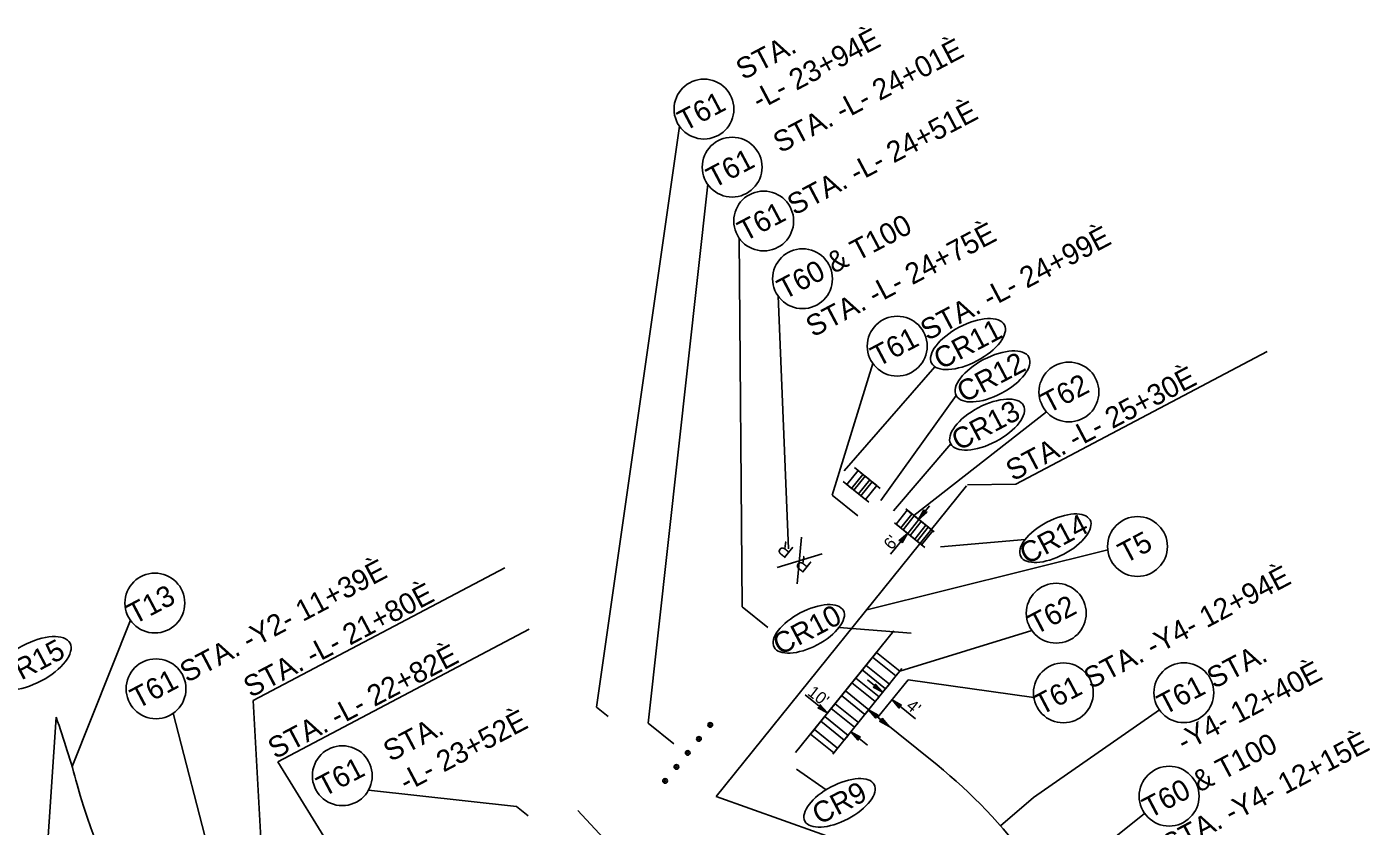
# Model space of a CAD drawing. Extents: x 1487421 to 1489048, y 497792 to 499463.
# Drawn here: x 1488599.3 to 1489047.9, y 499195.5 to 499462.7 of the extents above; entities that cross this region are included whole.
import ezdxf

# ---------------------------------------------------------------- set-up
doc = ezdxf.new("R2010")
doc.units = 0
for name, color, linetype in [('DEV TUBULAR MARKER PLAN VIEW CELL', 7, 'Continuous'), ('MARK RAILROAD SYMBOL CELL', 7, 'Continuous'), ('Prop Dimension', 7, 'Continuous'), ('Prop Mkg Min Skp 6ft White', 7, 'Continuous'), ('Prop Mkg Solid Dbl Yel Rpm 80ft', 7, 'Continuous'), ('Prop Mkg Solid White Crosswalks', 7, 'Continuous'), ('Prop Mkg Solid White Stop Bar', 7, 'Continuous'), ('Scratch_Level_3', 7, 'Continuous'), ('Scratch_Level_5', 7, 'Continuous'), ('Text', 7, 'Continuous')]:
    doc.layers.add(name, color=color, linetype=linetype)

msp = doc.modelspace()

# ---------------------------------------------------------------- linework, layer by layer
at = {"layer": 'DEV TUBULAR MARKER PLAN VIEW CELL'}
for centre, radius in [((1488827.51, 499229.29), 0.781), ((1488827.51, 499229.29), 0.332), ((1488823.74, 499224.62), 0.781), ((1488823.74, 499224.62), 0.332), ((1488819.98, 499219.95), 0.781), ((1488819.98, 499219.95), 0.332), ((1488816.21, 499215.28), 0.781), ((1488816.21, 499215.28), 0.332), ((1488812.44, 499210.61), 0.781), ((1488812.44, 499210.61), 0.332)]:
    msp.add_circle(centre, radius, dxfattribs=at)
at = {"layer": 'MARK RAILROAD SYMBOL CELL'}
for p, q in [((1488856.6, 499276.42), (1488857.96, 499292.1)), ((1488849.83, 499281.88), (1488864.87, 499286.53))]:
    msp.add_line(p, q, dxfattribs=at)
at = {"layer": 'Prop Dimension'}
for p, q in [((1488900.79, 499302.56), (1488897.12, 499298)), ((1488893.35, 499293.33), (1488887.71, 499286.34)), ((1488885.12, 499240.2), (1488879.98, 499244.35)), ((1488866.73, 499233.31), (1488859.17, 499239.4)), ((1488896.11, 499231.34), (1488888.24, 499237.69)), ((1488880.41, 499234.36), (1488887.3, 499228.8)), ((1488880.02, 499222.59), (1488874.51, 499227.04))]:
    msp.add_line(p, q, dxfattribs=at)
for points in [[(1488898.89, 499301.2), (1488897.12, 499298), (1488899.88, 499300.43), (1488899.09, 499300.47)], [(1488891.59, 499290.13), (1488893.35, 499293.33), (1488890.59, 499290.9), (1488891.38, 499290.86)], [(1488881.9, 499241.91), (1488885.12, 499240.2), (1488882.65, 499242.92), (1488882.63, 499242.13)], [(1488863.5, 499235.03), (1488866.73, 499233.31), (1488864.26, 499236.04), (1488864.23, 499235.25)], [(1488891.42, 499235.9), (1488888.24, 499237.69), (1488890.65, 499234.91), (1488890.69, 499235.7)], [(1488883.6, 499232.58), (1488880.41, 499234.36), (1488882.83, 499231.59), (1488882.87, 499232.37)], [(1488884.89, 499231.55), (1488887.3, 499228.8), (1488884.08, 499230.58), (1488884.84, 499230.79)], [(1488877.7, 499225.25), (1488874.51, 499227.04), (1488876.92, 499224.26), (1488876.96, 499225.05)]]:
    msp.add_lwpolyline(points, close=True, dxfattribs=at)
at = {"layer": 'Prop Mkg Min Skp 6ft White'}
msp.add_line((1488829.46, 499205.43), (1488913.13, 499309.18), dxfattribs=at)
at = {"layer": 'Prop Mkg Solid Dbl Yel Rpm 80ft'}
msp.add_line((1488883.53, 499231.85), (1488903.26, 499215.93), dxfattribs=at)
for centre, radius, start, end in [((1488292.94, 499121.08), 335, 15.2846, 19.3141), ((1488796.55, 499083.6), 170, 21.0099, 51.1156), ((1488809.02, 499262.12), 200, 195.2846, 229.8892)]:
    msp.add_arc(centre, radius, start, end, dxfattribs=at)
at = {"layer": 'Prop Mkg Solid White Crosswalks'}
for p, q in [((1488876.89, 499314.31), (1488873.13, 499309.64)), ((1488874.68, 499308.39), (1488878.45, 499313.06)), ((1488879.23, 499312.43), (1488875.46, 499307.76)), ((1488884.24, 499308.39), (1488875.67, 499315.3)), ((1488878.45, 499313.06), (1488876.89, 499314.31)), ((1488880.79, 499311.18), (1488879.23, 499312.43)), ((1488880.47, 499303.72), (1488871.91, 499310.63)), ((1488873.13, 499309.64), (1488874.68, 499308.39)), ((1488875.46, 499307.76), (1488877.02, 499306.51)), ((1488877.02, 499306.51), (1488880.79, 499311.18)), ((1488881.56, 499310.55), (1488877.8, 499305.88)), ((1488879.35, 499304.62), (1488883.12, 499309.29)), ((1488883.12, 499309.29), (1488881.56, 499310.55)), ((1488877.8, 499305.88), (1488879.35, 499304.62)), ((1488893.33, 499301.06), (1488889.56, 499296.39)), ((1488891.12, 499295.14), (1488894.88, 499299.81)), ((1488895.66, 499299.18), (1488891.9, 499294.51)), ((1488902.28, 499293.84), (1488892.8, 499301.49)), ((1488894.88, 499299.81), (1488893.33, 499301.06)), ((1488897.22, 499297.92), (1488895.66, 499299.18)), ((1488899.19, 499288.62), (1488889.03, 499296.82)), ((1488889.56, 499296.39), (1488891.12, 499295.14)), ((1488891.9, 499294.51), (1488893.45, 499293.25)), ((1488893.45, 499293.25), (1488897.22, 499297.92)), ((1488898, 499297.3), (1488894.23, 499292.62)), ((1488895.79, 499291.37), (1488899.55, 499296.04)), ((1488900.33, 499295.41), (1488896.57, 499290.74)), ((1488899.55, 499296.04), (1488898, 499297.3)), ((1488898.12, 499289.49), (1488901.89, 499294.16)), ((1488901.89, 499294.16), (1488900.33, 499295.41)), ((1488894.23, 499292.62), (1488895.79, 499291.37)), ((1488896.57, 499290.74), (1488898.12, 499289.49)), ((1488856.03, 499220.06), (1488888.86, 499260.76)), ((1488878.3, 499247.67), (1488879.55, 499249.22)), ((1488879.55, 499249.22), (1488878.3, 499247.67)), ((1488887.34, 499242.94), (1488879.55, 499249.22)), ((1488887.34, 499242.94), (1488879.55, 499249.22)), ((1488881.75, 499251.95), (1488883.01, 499253.5)), ((1488883.01, 499253.5), (1488881.75, 499251.95)), ((1488889.54, 499245.67), (1488881.75, 499251.95)), ((1488881.75, 499251.95), (1488889.54, 499245.67)), ((1488890.79, 499247.23), (1488883.01, 499253.5)), ((1488890.79, 499247.23), (1488883.01, 499253.5)), ((1488868.46, 499219.54), (1488891.53, 499248.14)), ((1488874.85, 499243.38), (1488876.1, 499244.94)), ((1488876.1, 499244.94), (1488874.85, 499243.38)), ((1488883.89, 499238.66), (1488876.1, 499244.94)), ((1488883.89, 499238.66), (1488876.1, 499244.94)), ((1488886.08, 499241.39), (1488878.3, 499247.67)), ((1488878.3, 499247.67), (1488886.08, 499241.39)), ((1488890.79, 499247.23), (1488889.54, 499245.67)), ((1488889.54, 499245.67), (1488890.79, 499247.23)), ((1488872.65, 499240.66), (1488871.39, 499239.1)), ((1488872.65, 499240.66), (1488871.39, 499239.1)), ((1488880.43, 499234.38), (1488872.65, 499240.66)), ((1488880.43, 499234.38), (1488872.65, 499240.66)), ((1488882.63, 499237.11), (1488874.85, 499243.38)), ((1488874.85, 499243.38), (1488882.63, 499237.11)), ((1488887.34, 499242.94), (1488886.08, 499241.39)), ((1488886.08, 499241.39), (1488887.34, 499242.94)), ((1488867.94, 499234.82), (1488869.2, 499236.38)), ((1488869.2, 499236.38), (1488867.94, 499234.82)), ((1488876.98, 499230.1), (1488869.2, 499236.38)), ((1488876.98, 499230.1), (1488869.2, 499236.38)), ((1488879.18, 499232.83), (1488871.39, 499239.1)), ((1488871.39, 499239.1), (1488879.18, 499232.83)), ((1488883.89, 499238.66), (1488882.63, 499237.11)), ((1488882.63, 499237.11), (1488883.89, 499238.66)), ((1488865.74, 499232.1), (1488864.49, 499230.54)), ((1488865.74, 499232.1), (1488864.49, 499230.54)), ((1488873.53, 499225.82), (1488865.74, 499232.1)), ((1488873.53, 499225.82), (1488865.74, 499232.1)), ((1488875.72, 499228.54), (1488867.94, 499234.82)), ((1488867.94, 499234.82), (1488875.72, 499228.54)), ((1488880.43, 499234.38), (1488879.18, 499232.83)), ((1488879.18, 499232.83), (1488880.43, 499234.38)), ((1488862.29, 499227.82), (1488861.04, 499226.26)), ((1488862.29, 499227.82), (1488861.04, 499226.26)), ((1488870.07, 499221.54), (1488862.29, 499227.82)), ((1488870.07, 499221.54), (1488862.29, 499227.82)), ((1488872.27, 499224.26), (1488864.49, 499230.54)), ((1488864.49, 499230.54), (1488872.27, 499224.26)), ((1488875.72, 499228.54), (1488876.98, 499230.1)), ((1488875.72, 499228.54), (1488876.98, 499230.1)), ((1488868.82, 499219.98), (1488861.04, 499226.26)), ((1488861.04, 499226.26), (1488868.82, 499219.98)), ((1488873.53, 499225.82), (1488872.27, 499224.26)), ((1488872.27, 499224.26), (1488873.53, 499225.82)), ((1488870.07, 499221.54), (1488868.82, 499219.98)), ((1488868.82, 499219.98), (1488870.07, 499221.54))]:
    msp.add_line(p, q, dxfattribs=at)
at = {"layer": 'Prop Mkg Solid White Stop Bar'}
for p, q in [((1488868.28, 499306.13), (1488876.84, 499299.23)), ((1488838.15, 499268.77), (1488846.72, 499261.85)), ((1488883.53, 499231.85), (1488893.6, 499244.33)), ((1488793.47, 499232.09), (1488789.58, 499235.22)), ((1488806.76, 499229.85), (1488815.34, 499222.93)), ((1488766.68, 499198.87), (1488762.79, 499202.01))]:
    msp.add_line(p, q, dxfattribs=at)
at = {"layer": 'Scratch_Level_3'}
for p, q in [((1488977.5, 499234.31), (1488935.42, 499205.07)), ((1488935.42, 499205.07), (1488924.5, 499195.52)), ((1488972.58, 499199.73), (1488950.83, 499182.38))]:
    msp.add_line(p, q, dxfattribs=at)
for centre in [(1488985.68, 499240.07), (1488980.76, 499205.49)]:
    msp.add_circle(centre, 10, dxfattribs=at)
at = {"layer": 'Scratch_Level_5'}
msp.add_line((1488883.01, 499253.5), (1488861.04, 499226.26), dxfattribs=at)
at = {"layer": 'Text'}
for p, q in [((1488817.25, 499429.4), (1488789.58, 499235.22)), ((1488826.66, 499410.01), (1488806.76, 499229.85)), ((1488837.2, 499391.99), (1488838.15, 499268.77)), ((1488850.17, 499372.69), (1488853.61, 499288.15)), ((1488929.52, 499309.82), (1489013.5, 499354.16)), ((1488881.78, 499350.17), (1488868.28, 499306.13)), ((1488872.23, 499314.22), (1488902.57, 499349.01)), ((1488884.49, 499304.33), (1488909.65, 499339.39)), ((1488939.85, 499333.93), (1488895.47, 499299.33)), ((1488888.77, 499300.88), (1488907.83, 499323.28)), ((1488929.52, 499309.82), (1488913.47, 499309.59)), ((1488932.64, 499291.25), (1488904.44, 499288.84)), ((1488960.25, 499287.85), (1488879.76, 499267.8)), ((1488674.91, 499237.45), (1488758.89, 499281.79)), ((1488633.88, 499264.29), (1488614.39, 499215.4)), ((1488683.08, 499216.92), (1488767.06, 499261.27)), ((1488870.56, 499261.91), (1488894.63, 499259.94)), ((1488934.89, 499260.88), (1488890.79, 499247.23)), ((1488935.57, 499238.5), (1488893.6, 499244.33)), ((1488674.91, 499237.45), (1488685.35, 499044.25)), ((1488601.93, 499126.36), (1488609.09, 499231.88)), ((1488648.19, 499233.22), (1488680.17, 499109.16)), ((1488683.08, 499216.92), (1488732.3, 499137.52)), ((1488866.19, 499207.63), (1488856.31, 499214.53)), ((1488713.39, 499207.47), (1488762.79, 499202.01)), ((1488918.19, 499173.82), (1488829.46, 499205.43)), ((1488827.84, 499152.76), (1488783.29, 499200.75))]:
    msp.add_line(p, q, dxfattribs=at)
for centre in [(1488825.42, 499435.16), (1488834.83, 499415.77), (1488845.37, 499397.75), (1488858.34, 499378.45), (1488889.96, 499355.93), (1488947.3, 499340.59), (1488970.19, 499288.95), (1488642.05, 499270.05), (1488943.07, 499266.64), (1488642.43, 499241.39), (1488945.45, 499240.01), (1488704.64, 499212.32)]:
    msp.add_circle(centre, 10, dxfattribs=at)
for centre, major_axis in [((1488913.6, 499356.62), (12.15, 6.41)), ((1488921.79, 499345.8), (12.15, 6.41)), ((1488919.97, 499329.69), (12.15, 6.41)), ((1488942.77, 499291.72), (11.57, 6.11)), ((1488860.41, 499261.41), (11.57, 6.11)), ((1488600.98, 499249.9), (12.73, 6.72)), ((1488870.71, 499203.25), (11.57, 6.11))]:
    msp.add_ellipse(centre, major_axis=major_axis, ratio=0.462467, dxfattribs=at)

# ---------------------------------------------------------------- texts
at = {"layer": 'MARK RAILROAD SYMBOL CELL'}
msp.add_text('R  R', height=4.556, rotation=141.1156, dxfattribs=at).set_placement((1488861.77, 499283.35))
at = {"layer": 'Prop Dimension'}
for s, rotation, p in [("6'", 51.1156, (1488888.17, 499287.56)), ("10'", 322.2334, (1488859.71, 499239.56)), ("4'", 321.1156, (1488892.66, 499235.07))]:
    msp.add_text(s, height=4, rotation=rotation, dxfattribs=at).set_placement(p)
at = {"layer": 'Scratch_Level_3'}
for s, p in [('T61 STA. ', (1488979.22, 499232.5)), ('-Y4- 12+40È', (1488985.76, 499220.12)), ('STA. -Y4- 12+15È', (1488980.84, 499185.53)), ('T60 & T100 ', (1488974.3, 499197.91))]:
    msp.add_text(s, height=7, rotation=27.835, dxfattribs=at).set_placement(p)
at = {"layer": 'Text'}
for s, rotation, p in [('-L- 23+94È', 27.835, (1488843.82, 499434.67)), ('STA.', 27.835, (1488838.51, 499444.73)), ('STA. -L- 24+01È', 27.835, (1488850.91, 499420.3)), ('T61', 27.835, (1488819.01, 499427.61)), ('T61 STA. -L- 24+51È', 27.835, (1488839.07, 499390.73)), ('T61', 27.835, (1488828.67, 499408.56)), ('T60 & T100', 27.835, (1488852.25, 499371.32)), ('STA. -L- 24+75È', 27.835, (1488861.84, 499358.77)), ('T61 STA. -L- 24+99È', 27.835, (1488883.53, 499348.85)), ('CR11', 27.8351, (1488904.53, 499347.94)), ('CR12', 27.8351, (1488912.28, 499336.88)), ('STA. -L- 25+30È', 27.835, (1488928.65, 499310.65)), ('T62', 27.835, (1488940.42, 499333.27)), ('CR13', 27.8351, (1488910.5, 499320.79)), ('CR14', 27.8351, (1488933.23, 499282.79)), ('T5', 27.835, (1488966.1, 499283.1)), ('T61 STA. -Y2- 11+39È', 27.835, (1488636.23, 499234.53)), ('T61 STA. -Y4- 12+94È', 27.835, (1488938.07, 499232.42)), ('STA. -L- 21+80È', 27.835, (1488674.04, 499238.28)), ('T13', 27.835, (1488635.2, 499262.75)), ('T62', 27.835, (1488936.19, 499259.31)), ('CR10', 27.8351, (1488850.85, 499252.47)), ('CR15', 27.8351, (1488591.47, 499240.98)), ('STA. -L- 22+82È', 27.835, (1488682.21, 499217.76)), ('-L- 23+52È', 27.835, (1488726.03, 499206.8)), ('STA.', 27.835, (1488720.72, 499216.86)), ('T61', 27.835, (1488698.48, 499205.11)), ('CR9', 27.8351, (1488863.95, 499195.78))]:
    msp.add_text(s, height=7, rotation=rotation, dxfattribs=at).set_placement(p)

doc.saveas('drawing.dxf')
